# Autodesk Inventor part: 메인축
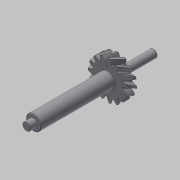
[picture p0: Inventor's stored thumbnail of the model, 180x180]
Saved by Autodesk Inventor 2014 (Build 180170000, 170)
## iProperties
Created: 2016-12
Part Number: 메인축
Material: 강철, 탄소
Document SubType Name: Modeling
Designer: mduedu
Categories: <?xml version="1.0" encoding="UTF-16"?> <MemberInstance><Categories><FamilyTemplate><FamilyTemplateParameter ValueType="xs:double" Id="1" ObjectReferenceKey="da
Density: 7.87 g/cm^3
Mass: 199.41 g
Surface Area: 86.9446 cm^2
Volume: 25.338 cm^3
Appearance: 기본값
CustomPartVersion: 1
Author: mduedu
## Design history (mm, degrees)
sketch "Sketch1"
  geometry: C1 r 19.321 at (0, 0)
  constraints: 1 centre point
  dimensions: "d0" = 38.64102 diameter of C1 (= da_da)
extrude "Extrusion1" new body sketch "Sketch1" distance "d1" = 10 (= da_b); taper "d2" = 0 deg
workplane "Work Plane2"
sketch "Sketch2"
  geometry: C1 r 19.321 at (0, 0) reference; C2 r 17.321 at (0, 0)
  constraints: 1 centre point, 1 coincident
  dimensions: "d3" = 34.64102 diameter of C2 (= da_dw)
feature "피치 지름" sketch "Sketch2" dims "d4" = 10, "d5" = 0
workplane "Work Plane8"
workplane "Work Plane9"
feature "스퍼 기어" dims "da_b" = 10, "da_d" = 34.64102, "da_aw" = 43.87862, "da_da" = 38.64102, "da_df" = 29.64102, "da_dw" = 34.64102, angle "da_beta" = 30 deg, "da_lefttooth" = 0, "da_righttooth" = 10
sketch "스케치3"
  geometry: C1 r 7.5 at (0, 0); 1 further point
  constraints: 1 centre point, 1 coincident
  dimensions: "d49" = 15 diameter of C1
extrude "돌출2" join sketch "스케치3" distance "d50" = 74; taper "d51" = 0 deg
sketch "스케치4"
  geometry: C1 r 4 at (0, 0); 1 further point
  constraints: 1 centre point, 1 coincident
  dimensions: "d52" = 8 diameter of C1
extrude "돌출3" join sketch "스케치4" distance "d53" = 7; taper "d54" = 0 deg
sketch "스케치5"
  geometry: C1 r 7.5 at (0, 0) reference; 1 further point
extrude "돌출4" join sketch "스케치5" distance "d55" = 6; taper "d56" = 0 deg
sketch "스케치6"
  geometry: C1 r 4 at (0, 0); 1 further point
  constraints: 1 centre point, 1 coincident
  dimensions: "d57" = 8 diameter of C1
extrude "돌출5" join sketch "스케치6" distance "d58" = 30; taper "d59" = 0 deg
chamfer "모따기1" distance "d60" = 0.5; stored, may be unused: second distance "d61" = 2, angle "d62" = 45 deg
fillet "모깎기1" dims "d63" = 0.5
sketch "스케치7" dims "d64" = 25
  geometry: C1 r 1 at (0, 12.5); 2 further points
  constraints: 2 vertical alignment, 1 centre point, 1 coincident, 2 other
  dimensions: "d65" = 2 diameter of C1
extrude "돌출6" join sketch "스케치7" distance "d66" = 0.5; taper "d67" = 0 deg
body "Solid1"
body "Srf1"
other parameters: "d16" = 43.87862 (= da_aw), "d17" = 0, "d34" = 12 deg (computed from da_z), "d39" = 0, "d41" = 0, "d43" = 43.87862 (= da_aw), "d46" = 43.87862 (= da_aw), "d47" = 0, "d48" = 0
